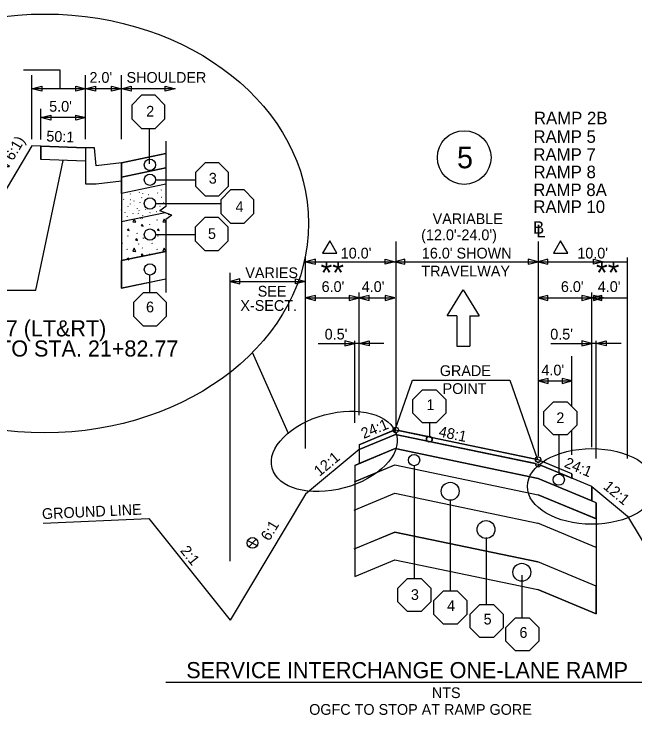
# Model space of a CAD drawing. Extents: x 4932 to 5887, y 4809 to 5473.
# Drawn here: x 5206.1 to 5275.5, y 5134.9 to 5213.3 of the extents above; entities that cross this region are included whole.
import ezdxf

# ---------------------------------------------------------------- set-up
doc = ezdxf.new("R2010")
doc.units = 0
for name, color, linetype in [('Level 2', 7, 'Continuous'), ('Level 20', 7, 'Continuous'), ('Level 25', 7, 'Continuous'), ('RD_QTY_Intermediate', 7, 'Continuous'), ('RD_QTY_Sub_Base', 7, 'Continuous'), ('RD_QTY_Surf_Course', 7, 'Continuous'), ('RD_SHT_Typical', 7, 'Continuous'), ('RD_TX_TypSect', 7, 'Continuous'), ('RD_XS_CurbBase', 7, 'Continuous'), ('RD_XS_CurbFront', 7, 'Continuous'), ('RD_XS_CurbTop', 7, 'Continuous'), ('RD_XS_ExGround', 7, 'Continuous'), ('typical_on', 7, 'Continuous')]:
    doc.layers.add(name, color=color, linetype=linetype)

msp = doc.modelspace()

# ---------------------------------------------------------------- linework, layer by layer
at = {"layer": 'Level 2'}
for p, q in [((5244.703, 5163.036), (5244.703, 5163.036)), ((5244.703, 5162.981), (5244.703, 5162.981))]:
    msp.add_line(p, q, dxfattribs=at)
at = {"layer": 'Level 20'}
for p, q in [((5254.517, 5179.537), (5256.339, 5182.451)), ((5256.339, 5182.451), (5258.123, 5179.527)), ((5255.609, 5179.536), (5254.517, 5179.537)), ((5255.609, 5179.536), (5255.609, 5176.136)), ((5257.066, 5179.527), (5258.123, 5179.527)), ((5257.066, 5179.527), (5257.066, 5176.127)), ((5255.609, 5176.136), (5257.066, 5176.127))]:
    msp.add_line(p, q, dxfattribs=at)
at = {"layer": 'Level 25'}
for p, q in [((5223.1, 5197.665), (5218.139, 5196.631)), ((5223.1, 5194.243), (5218.139, 5193.209)), ((5248.724, 5166.803), (5250.667, 5172.338)), ((5250.667, 5172.338), (5261.523, 5172.338)), ((5261.523, 5172.338), (5264.629, 5163.489))]:
    msp.add_line(p, q, dxfattribs=at)
msp.add_circle((5256.437, 5197.225), 3, dxfattribs=at)
at = {"layer": 'RD_QTY_Intermediate'}
for p, q in [((5218.139, 5195.036), (5223.1, 5196.058)), ((5223.1, 5196.058), (5223.1, 5194.243)), ((5223.1, 5196.058), (5223.1, 5196.058)), ((5218.139, 5193.769), (5218.139, 5195.036)), ((5218.139, 5193.209), (5218.139, 5194.871)), ((5218.139, 5194.871), (5218.139, 5193.769)), ((5223.1, 5194.243), (5218.139, 5193.209)), ((5223.1, 5194.243), (5223.1, 5194.243)), ((5264.696, 5161.376), (5248.724, 5164.704)), ((5244.203, 5161.011), (5248.696, 5162.883)), ((5244.203, 5162.82), (5244.203, 5161.011)), ((5248.696, 5162.883), (5264.694, 5159.55)), ((5270.694, 5158.858), (5264.696, 5161.376)), ((5264.694, 5159.55), (5271.193, 5156.842)), ((5271.193, 5158.65), (5270.694, 5158.86)), ((5271.193, 5156.842), (5271.193, 5158.65))]:
    msp.add_line(p, q, dxfattribs=at)
for points in [[(5248.724, 5164.704), (5244.703, 5163.029), (5244.203, 5162.82)], [(5270.694, 5158.86), (5270.694, 5158.858)]]:
    msp.add_lwpolyline(points, dxfattribs=at)
at = {"layer": 'RD_QTY_Sub_Base'}
for p, q in [((5218.154, 5185.715), (5223.1, 5186.732)), ((5223.1, 5186.732), (5223.1, 5183.64)), ((5223.1, 5186.732), (5223.1, 5186.732)), ((5218.161, 5182.616), (5218.154, 5185.715)), ((5223.1, 5183.64), (5218.161, 5182.616))]:
    msp.add_line(p, q, dxfattribs=at)
at = {"layer": 'RD_QTY_Surf_Course'}
for p, q in [((5218.139, 5196.631), (5223.1, 5197.665)), ((5223.1, 5197.665), (5223.1, 5196.069)), ((5223.1, 5197.665), (5223.1, 5197.665)), ((5223.1, 5197.665), (5223.1, 5197.665)), ((5218.139, 5195.036), (5218.139, 5196.631)), ((5223.1, 5196.069), (5218.139, 5195.036)), ((5248.76, 5166.292), (5244.703, 5164.602)), ((5264.402, 5163.033), (5248.76, 5166.292)), ((5244.703, 5163.029), (5248.724, 5164.704)), ((5244.703, 5164.602), (5244.703, 5163.029)), ((5248.724, 5164.704), (5264.696, 5161.376)), ((5264.696, 5161.376), (5270.694, 5158.86)), ((5270.694, 5158.86), (5270.694, 5160.473))]:
    msp.add_line(p, q, dxfattribs=at)
msp.add_lwpolyline([(5270.694, 5160.473), (5267.058, 5161.988), (5264.973, 5162.857)], dxfattribs=at)
msp.add_circle((5267, 5161.225), 0.63, dxfattribs=at)
msp.add_arc((5264.696, 5162.972), 0.3, 168.23191, 337.38014, dxfattribs=at)
at = {"layer": 'RD_SHT_Typical'}
for p, q in [((5208.143, 5198.515), (5203.033, 5189.997)), ((5214.139, 5198.298), (5208.143, 5198.515)), ((5209.139, 5198.479), (5209.139, 5196.988)), ((5209.139, 5196.988), (5209.139, 5198.479)), ((5209.139, 5198.479), (5214.139, 5198.298)), ((5209.139, 5198.479), (5214.139, 5198.298)), ((5214.139, 5198.298), (5209.139, 5198.479)), ((5223.1, 5199.043), (5223.1, 5191.766)), ((5214.139, 5198.298), (5214.139, 5196.807)), ((5214.139, 5196.807), (5209.139, 5196.988)), ((5214.139, 5196.807), (5209.139, 5196.988)), ((5218.139, 5196.631), (5218.139, 5182.6)), ((5218.139, 5195.036), (5223.1, 5196.058)), ((5218.139, 5193.209), (5218.139, 5190.958)), ((5223.1, 5190.29), (5223.1, 5182.128)), ((5246.645, 5165.937), (5248.724, 5166.803)), ((5248.501, 5166.71), (5246.645, 5165.937)), ((5252.387, 5166.04), (5249.083, 5166.728)), ((5244.703, 5164.602), (5248.76, 5166.292)), ((5244.703, 5164.602), (5248.76, 5166.292)), ((5244.703, 5165.128), (5246.645, 5165.937)), ((5246.645, 5165.937), (5244.703, 5165.128)), ((5248.76, 5166.292), (5252.266, 5165.561)), ((5244.703, 5165.128), (5244.703, 5163.029)), ((5244.703, 5165.128), (5244.703, 5164.602)), ((5252.72, 5165.467), (5264.402, 5163.033)), ((5244.703, 5164.602), (5238.706, 5159.604)), ((5244.203, 5162.82), (5248.724, 5164.704)), ((5268.472, 5161.888), (5264.629, 5163.489)), ((5268.472, 5161.888), (5264.966, 5163.349)), ((5244.176, 5160.999), (5248.696, 5162.883)), ((5244.203, 5162.82), (5244.203, 5150.416)), ((5264.402, 5163.033), (5264.696, 5162.972)), ((5270.694, 5160.473), (5264.696, 5162.972)), ((5264.696, 5162.972), (5264.973, 5162.857)), ((5268.472, 5161.888), (5268.472, 5161.4)), ((5268.472, 5161.4), (5268.472, 5161.888)), ((5271.193, 5158.65), (5264.672, 5161.367)), ((5270.694, 5160.473), (5270.694, 5158.858)), ((5270.694, 5160.473), (5274.692, 5157.141)), ((5238.706, 5159.604), (5230.27, 5145.544)), ((5244.153, 5157.823), (5248.674, 5159.707)), ((5271.216, 5156.833), (5264.694, 5159.55)), ((5271.193, 5158.65), (5271.193, 5146.229)), ((5274.692, 5157.141), (5282.696, 5143.801)), ((5221.185, 5156.901), (5230.27, 5145.544)), ((5271.193, 5153.657), (5264.672, 5156.374)), ((5244.16, 5153.492), (5248.68, 5155.376)), ((5244.203, 5150.416), (5248.674, 5152.279)), ((5271.193, 5149.327), (5264.654, 5152.052)), ((5271.193, 5146.229), (5264.654, 5148.953))]:
    msp.add_line(p, q, dxfattribs=at)
for points in [[(5223.036, 5191.049), (5218.139, 5190.029)], [(5223.1, 5186.732), (5218.139, 5185.699)], [(5223.1, 5183.634), (5218.139, 5182.6)], [(5248.724, 5166.803), (5263.699, 5163.683), (5264.629, 5163.489)], [(5248.76, 5166.292), (5264.696, 5162.972)], [(5264.401, 5163.537), (5263.699, 5163.683), (5252.8, 5165.954)], [(5248.724, 5164.704), (5264.696, 5161.376)], [(5248.696, 5162.883), (5264.694, 5159.55)], [(5264.973, 5162.857), (5267.058, 5161.988), (5268.472, 5161.399)], [(5268.472, 5161.399), (5268.472, 5161.4)], [(5248.674, 5159.707), (5264.672, 5156.374)], [(5248.674, 5155.377), (5264.672, 5152.044)], [(5248.674, 5152.279), (5264.672, 5148.946)]]:
    msp.add_lwpolyline(points, dxfattribs=at)
for centre, radius, start, end in [((5248.79, 5166.789), 0.3, 195.36042, 348.23191), ((5252.541, 5165.746), 0.332, 117.69811, 213.83802), ((5252.541, 5165.746), 0.332, 302.6258, 38.76571), ((5264.694, 5163.476), 0.3, 168.23191, 334.96624)]:
    msp.add_arc(centre, radius, start, end, dxfattribs=at)
at = {"layer": 'RD_TX_TypSect'}
for p, q in [((5207.207, 5207.028), (5211.242, 5207.028)), ((5208.143, 5199.278), (5208.143, 5206.443)), ((5211.242, 5207.028), (5211.242, 5204.919)), ((5214.141, 5199.278), (5214.141, 5206.443)), ((5218.139, 5199.278), (5218.139, 5206.443)), ((5214.141, 5204.911), (5208.143, 5204.911)), ((5218.139, 5204.911), (5214.141, 5204.911)), ((5224.137, 5204.911), (5218.139, 5204.911)), ((5209.139, 5199.242), (5209.139, 5202.669)), ((5214.141, 5201.681), (5209.139, 5201.681)), ((5221.261, 5196.531), (5221.261, 5200.482)), ((5208.575, 5182.385), (5211.639, 5196.897)), ((5221.948, 5194.738), (5226.359, 5194.738)), ((5219.139, 5193.139), (5219.128, 5193.172)), ((5220.141, 5193.329), (5220.13, 5193.363)), ((5220.529, 5193.185), (5220.518, 5193.218)), ((5221.116, 5193.105), (5221.15, 5193.098)), ((5222.189, 5193.232), (5222.178, 5193.265)), ((5222.623, 5193.587), (5222.612, 5193.621)), ((5218.394, 5192.52), (5218.383, 5192.553)), ((5219.12, 5192.548), (5219.155, 5192.541)), ((5219.528, 5192.367), (5219.545, 5192.384)), ((5220.234, 5192.184), (5220.223, 5192.218)), ((5220.396, 5192.73), (5220.412, 5192.746)), ((5222.573, 5192.796), (5222.608, 5192.788)), ((5218.211, 5191.785), (5218.228, 5191.802)), ((5218.878, 5191.719), (5218.895, 5191.735)), ((5219.145, 5192.018), (5219.161, 5192.035)), ((5219.628, 5191.852), (5219.645, 5191.868)), ((5219.895, 5191.545), (5219.888, 5191.537)), ((5219.908, 5191.552), (5219.895, 5191.545)), ((5220.854, 5191.417), (5220.843, 5191.45)), ((5221.948, 5192.084), (5229.236, 5192.084)), ((5223.1, 5191.766), (5222.416, 5191.28)), ((5222.445, 5191.785), (5222.462, 5191.802)), ((5222.845, 5192.168), (5222.862, 5192.184)), ((5218.146, 5191.355), (5218.135, 5191.388)), ((5218.555, 5191.096), (5218.572, 5191.113)), ((5218.813, 5190.638), (5218.802, 5190.671)), ((5219.076, 5191.324), (5219.065, 5191.357)), ((5219.465, 5190.979), (5219.453, 5191.012)), ((5220.048, 5190.984), (5220.037, 5191.017)), ((5220.11, 5191.262), (5220.099, 5191.296)), ((5220.545, 5190.716), (5220.534, 5190.749)), ((5221.326, 5191.049), (5221.343, 5191.066)), ((5222.015, 5191.193), (5222.049, 5191.186)), ((5223.777, 5190.772), (5222.416, 5191.28)), ((5223.777, 5190.772), (5223.1, 5190.29)), ((5223.411, 5190.849), (5223.383, 5190.807)), ((5223.439, 5190.865), (5223.411, 5190.823)), ((5218.208, 5189.988), (5218.197, 5190.022)), ((5218.679, 5190.152), (5218.696, 5190.169)), ((5219.284, 5190.245), (5219.301, 5190.261)), ((5219.754, 5189.997), (5219.611, 5190.266)), ((5220.278, 5190.45), (5220.312, 5190.443)), ((5220.502, 5190.346), (5220.474, 5190.409)), ((5222.159, 5190.185), (5222.131, 5190.248)), ((5221.285, 5189.738), (5221.257, 5189.696)), ((5218.88, 5188.409), (5218.852, 5188.472)), ((5219.943, 5188.696), (5219.915, 5188.759)), ((5221.948, 5188.608), (5226.359, 5188.608)), ((5222.229, 5188.409), (5222.201, 5188.472)), ((5218.244, 5187.598), (5218.216, 5187.661)), ((5220.062, 5187.582), (5220.034, 5187.54)), ((5220.09, 5187.598), (5220.062, 5187.556)), ((5220.567, 5188.234), (5220.56, 5188.171)), ((5221.593, 5187.598), (5221.565, 5187.661)), ((5248.79, 5187.854), (5248.79, 5167.151)), ((5264.694, 5187.854), (5264.694, 5163.838)), ((5218.81, 5186.919), (5218.782, 5186.982)), ((5220.502, 5187.08), (5220.474, 5187.143)), ((5222.159, 5186.919), (5222.131, 5186.982)), ((5221.285, 5186.472), (5221.257, 5186.43)), ((5238.706, 5164.692), (5238.706, 5186.061)), ((5274.692, 5163.609), (5274.692, 5186.061)), ((5238.706, 5185.575), (5248.702, 5185.575)), ((5248.702, 5185.575), (5264.696, 5185.575)), ((5264.696, 5185.575), (5274.692, 5185.575)), ((5221.312, 5182.098), (5221.312, 5184.098)), ((5230.27, 5152.11), (5230.27, 5184.348)), ((5230.27, 5183.384), (5238.706, 5183.384)), ((5204.54, 5182.385), (5208.575, 5182.385)), ((5244.703, 5168.43), (5244.703, 5182.156)), ((5270.694, 5164.873), (5270.694, 5182.156)), ((5238.706, 5181.538), (5244.703, 5181.538)), ((5244.703, 5181.538), (5248.702, 5181.538)), ((5264.696, 5181.538), (5270.694, 5181.538)), ((5270.694, 5181.538), (5274.692, 5181.538)), ((5244.203, 5167.573), (5244.203, 5176.735)), ((5271.193, 5163.609), (5271.193, 5176.735)), ((5240.125, 5176.46), (5244.203, 5176.46)), ((5247.468, 5176.46), (5244.203, 5176.46)), ((5266.106, 5176.46), (5270.694, 5176.46)), ((5273.959, 5176.46), (5270.694, 5176.46)), ((5236.773, 5166.446), (5232.791, 5175.443)), ((5268.473, 5169.393), (5268.473, 5175.015)), ((5264.726, 5172.26), (5268.473, 5172.26)), ((5252.542, 5167.562), (5252.542, 5166.078)), ((5268.473, 5164.002), (5268.473, 5166.76)), ((5267.058, 5161.848), (5267.058, 5166.23)), ((5250.879, 5150.173), (5250.879, 5162.816)), ((5254.895, 5148.789), (5254.895, 5158.998)), ((5248.674, 5155.377), (5244.203, 5153.51)), ((5258.944, 5147.277), (5258.944, 5154.75)), ((5232.24, 5154.427), (5233.312, 5153.88)), ((5232.363, 5153.734), (5233.189, 5154.578)), ((5244.203, 5153.51), (5244.203, 5150.416)), ((5244.203, 5150.416), (5248.674, 5152.279)), ((5248.674, 5152.279), (5264.654, 5148.95)), ((5271.193, 5149.327), (5264.672, 5152.044)), ((5262.92, 5145.784), (5262.92, 5150.55)), ((5271.193, 5146.229), (5271.193, 5149.327)), ((5223.094, 5138.601), (5281.463, 5138.601))]:
    msp.add_line(p, q, dxfattribs=at)
for points in [[(5209.246, 5205.186), (5209.246, 5204.636), (5208.143, 5204.911)], [(5213.038, 5204.636), (5213.038, 5205.186), (5214.141, 5204.911)], [(5215.243, 5205.186), (5215.243, 5204.636), (5214.141, 5204.911)], [(5217.037, 5204.636), (5217.037, 5205.186), (5218.139, 5204.911)], [(5219.242, 5205.186), (5219.242, 5204.636), (5218.139, 5204.911)], [(5223.034, 5204.636), (5223.034, 5205.186), (5224.137, 5204.911)], [(5210.241, 5201.956), (5210.241, 5201.406), (5209.139, 5201.681)], [(5213.038, 5201.406), (5213.038, 5201.956), (5214.141, 5201.681)], [(5241.422, 5187.91), (5240.623, 5186.525), (5242.221, 5186.525)], [(5267.214, 5187.91), (5266.415, 5186.525), (5268.013, 5186.525)], [(5239.808, 5185.3), (5239.808, 5185.85), (5238.706, 5185.575)], [(5247.599, 5185.3), (5247.599, 5185.85), (5248.702, 5185.575)], [(5249.804, 5185.3), (5249.804, 5185.85), (5248.702, 5185.575)], [(5263.593, 5185.85), (5263.593, 5185.3), (5264.696, 5185.575)], [(5265.799, 5185.3), (5265.799, 5185.85), (5264.696, 5185.575)], [(5270.882, 5185.3), (5270.882, 5185.85), (5271.984, 5185.575)], [(5231.373, 5183.11), (5231.373, 5183.659), (5230.27, 5183.384)], [(5237.603, 5183.11), (5237.603, 5183.659), (5238.706, 5183.384)], [(5239.808, 5181.263), (5239.808, 5181.813), (5238.706, 5181.538)], [(5243.601, 5181.813), (5243.601, 5181.263), (5244.703, 5181.538)], [(5245.806, 5181.263), (5245.806, 5181.813), (5244.703, 5181.538)], [(5247.599, 5181.813), (5247.599, 5181.263), (5248.702, 5181.538)], [(5265.799, 5181.263), (5265.799, 5181.813), (5264.696, 5181.538)], [(5269.591, 5181.813), (5269.591, 5181.263), (5270.694, 5181.538)], [(5271.796, 5181.263), (5271.796, 5181.813), (5270.694, 5181.538)], [(5270.882, 5181.813), (5270.882, 5181.263), (5271.984, 5181.538)], [(5243.101, 5176.735), (5243.101, 5176.186), (5244.203, 5176.46)], [(5245.806, 5176.735), (5245.806, 5176.186), (5244.703, 5176.46)], [(5269.591, 5176.735), (5269.591, 5176.186), (5270.694, 5176.46)], [(5272.296, 5176.735), (5272.296, 5176.186), (5271.193, 5176.46)], [(5265.828, 5171.985), (5265.828, 5172.535), (5264.726, 5172.26)], [(5267.37, 5172.535), (5267.37, 5171.985), (5268.473, 5172.26)]]:
    msp.add_lwpolyline(points, close=True, dxfattribs=at)
for points in [[(5219.518, 5190.246), (5219.418, 5190.025), (5219.747, 5189.997)], [(5223.1, 5190.004), (5222.915, 5190.353), (5222.768, 5190.025), (5223.096, 5189.997)], [(5219.018, 5189.056), (5218.935, 5189.231), (5218.795, 5189.126), (5219.018, 5189.056)], [(5220.551, 5189.556), (5220.467, 5189.731), (5220.327, 5189.626), (5220.551, 5189.556)], [(5222.368, 5189.056), (5222.284, 5189.231), (5222.144, 5189.126), (5222.368, 5189.056)], [(5219.929, 5187.962), (5219.845, 5188.137), (5219.705, 5188.032), (5219.929, 5187.962)], [(5223.1, 5188.066), (5223.054, 5188.032), (5223.1, 5188.018)], [(5219.754, 5186.73), (5219.565, 5187.087), (5219.418, 5186.758), (5219.747, 5186.73)], [(5223.1, 5186.738), (5222.915, 5187.087), (5222.768, 5186.758), (5223.096, 5186.73)], [(5219.009, 5185.811), (5218.935, 5185.965), (5218.795, 5185.86), (5218.975, 5185.804)], [(5220.551, 5186.29), (5220.467, 5186.465), (5220.327, 5186.36), (5220.551, 5186.29)], [(5264.672, 5152.044), (5264.654, 5152.048), (5248.674, 5155.377)], [(5264.654, 5148.95), (5264.654, 5148.953)], [(5264.654, 5148.953), (5264.672, 5148.946), (5271.193, 5146.229)]]:
    msp.add_lwpolyline(points, dxfattribs=at)
for centre, radius in [((5221.319, 5196.408), 0.63), ((5221.319, 5194.738), 0.63), ((5221.319, 5192.084), 0.63), ((5221.319, 5188.608), 0.63), ((5221.319, 5184.727), 0.63), ((5248.79, 5166.789), 0.3), ((5252.541, 5165.746), 0.332), ((5250.842, 5163.421), 0.63), ((5264.694, 5163.476), 0.3), ((5267, 5161.225), 0.63), ((5254.876, 5159.932), 1), ((5258.874, 5155.658), 1), ((5232.781, 5154.159), 0.6), ((5262.877, 5150.879), 1), ((5262.877, 5150.879), 1)]:
    msp.add_circle(centre, radius, dxfattribs=at)
for centre, major_axis, ratio in [((5209.58, 5189.865), (-29.478, 0), 0.793631), ((5241.924, 5164.384), (-6.951, -1.869), 0.587586), ((5270.694, 5160.473), (-7.198, 0), 0.587586)]:
    msp.add_ellipse(centre, major_axis=major_axis, ratio=ratio, dxfattribs=at)
at = {"layer": 'RD_XS_CurbBase'}
for p, q in [((5214.139, 5198.298), (5214.139, 5194.298)), ((5215.306, 5194.298), (5218.139, 5194.631)), ((5214.139, 5194.298), (5215.306, 5194.298))]:
    msp.add_line(p, q, dxfattribs=at)
at = {"layer": 'RD_XS_CurbFront'}
msp.add_line((5218.139, 5196.631), (5218.139, 5195.135), dxfattribs=at)
at = {"layer": 'RD_XS_CurbTop'}
for p, q in [((5215.139, 5198.298), (5214.139, 5198.298)), ((5215.306, 5196.298), (5215.139, 5198.298)), ((5218.139, 5196.631), (5215.306, 5196.298))]:
    msp.add_line(p, q, dxfattribs=at)
at = {"layer": 'RD_XS_ExGround'}
msp.add_line((5209.392, 5156.364), (5221.185, 5156.901), dxfattribs=at)
at = {"layer": 'typical_on'}
for points in [[(5219.295, 5203.093), (5219.295, 5201.563), (5220.376, 5200.482), (5221.906, 5200.482), (5222.987, 5201.563), (5222.987, 5203.093), (5221.906, 5204.175), (5220.376, 5204.175)], [(5226.41, 5195.546), (5226.41, 5194.017), (5227.492, 5192.935), (5229.021, 5192.935), (5230.103, 5194.017), (5230.103, 5195.546), (5229.021, 5196.628), (5227.492, 5196.628)], [(5229.236, 5192.515), (5229.236, 5190.986), (5230.317, 5189.904), (5231.847, 5189.904), (5232.928, 5190.986), (5232.928, 5192.515), (5231.847, 5193.597), (5230.317, 5193.597)], [(5226.382, 5189.451), (5226.382, 5187.921), (5227.463, 5186.84), (5228.993, 5186.84), (5230.075, 5187.921), (5230.075, 5189.451), (5228.993, 5190.533), (5227.463, 5190.533)], [(5219.479, 5181.016), (5219.479, 5179.486), (5220.561, 5178.405), (5222.09, 5178.405), (5223.172, 5179.486), (5223.172, 5181.016), (5222.091, 5182.098), (5220.561, 5182.098)], [(5254.388, 5170.173), (5254.388, 5168.643), (5253.307, 5167.562), (5251.777, 5167.562), (5250.696, 5168.643), (5250.696, 5170.173), (5251.777, 5171.255), (5253.307, 5171.255)], [(5269.024, 5168.841), (5269.024, 5167.312), (5267.943, 5166.23), (5266.413, 5166.23), (5265.332, 5167.312), (5265.332, 5168.841), (5266.413, 5169.923), (5267.943, 5169.923)], [(5252.725, 5149.092), (5252.725, 5147.562), (5251.644, 5146.481), (5250.114, 5146.48), (5249.032, 5147.562), (5249.032, 5149.092), (5250.114, 5150.173), (5251.644, 5150.173)], [(5256.741, 5147.708), (5256.741, 5146.178), (5255.66, 5145.096), (5254.13, 5145.096), (5253.048, 5146.178), (5253.048, 5147.708), (5254.13, 5148.789), (5255.66, 5148.789)], [(5260.79, 5146.195), (5260.79, 5144.666), (5259.709, 5143.584), (5258.179, 5143.584), (5257.098, 5144.666), (5257.098, 5146.195), (5258.179, 5147.277), (5259.709, 5147.277)], [(5264.766, 5144.703), (5264.767, 5143.173), (5263.685, 5142.092), (5262.155, 5142.091), (5261.074, 5143.173), (5261.074, 5144.703), (5262.155, 5145.784), (5263.685, 5145.784)]]:
    msp.add_lwpolyline(points, close=True, dxfattribs=at)

# ---------------------------------------------------------------- texts
at = {"layer": 'Level 25'}
msp.add_text('50:1', height=1.2, rotation=357.93101, dxfattribs=at).set_placement((5209.733, 5199.023))
msp.add_text('5', height=2.4, dxfattribs=at).set_placement((5255.633, 5196.025))
at = {"layer": 'RD_TX_TypSect'}
for s, height, p in [("2.0'", 1.2, (5214.568, 5205.573)), ('SHOULDER', 1.2, (5218.709, 5205.573)), ("5.0'", 1.2, (5210.068, 5202.343)), ('2', 1.2, (5220.906, 5201.796)), ('RAMP 2B', 1.4, (5264.229, 5200.94)), ('RAMP 5', 1.4, (5264.177, 5198.862)), ('RAMP 7', 1.4, (5264.166, 5196.858)), ('RAMP 8', 1.4, (5264.177, 5194.916)), ('3', 1.2, (5227.903, 5194.312)), ('RAMP 8A', 1.4, (5264.154, 5192.92)), ('4', 1.2, (5230.887, 5191.133)), ('RAMP 10', 1.4, (5264.167, 5191.031)), ('B', 1.4, (5264.122, 5188.7)), ('5', 1.2, (5227.806, 5188.118)), ('L', 1.4, (5264.494, 5188.313)), ("10.0'", 1.2, (5242.642, 5185.939)), ("16.0' SHOWN", 1.2, (5251.706, 5185.939)), ("10.0'", 1.2, (5269.072, 5185.939)), ('**', 2.5, (5240.394, 5183.112)), ('**', 2.5, (5271.168, 5183.112)), ('VARIES', 1.2, (5231.984, 5183.748)), ('TRAVELWAY', 1.2, (5251.656, 5183.939)), ('SEE', 1.2, (5233.365, 5181.686)), ("6.0'", 1.2, (5240.505, 5182.199)), ("4.0'", 1.2, (5244.987, 5182.199)), ("6.0'", 1.2, (5267.241, 5182.199)), ("4.0'", 1.2, (5271.363, 5182.199)), ('X-SECT.', 1.2, (5231.429, 5180.089)), ('6', 1.2, (5220.888, 5179.923)), ('RAMP 7 (LT&RT)', 1.8, (5197.591, 5177.239)), ("0.5'", 1.2, (5240.848, 5176.887)), ("0.5'", 1.2, (5266.052, 5176.887)), ('STA. 21+16.64 TO STA. 21+82.77', 1.8, (5187.57, 5174.986)), ('GRADE', 1.2, (5253.712, 5172.806)), ("4.0'", 1.2, (5265.067, 5172.875)), ('POINT', 1.2, (5254.024, 5170.806)), ('1', 1.2, (5252.224, 5168.999)), ('2', 1.2, (5266.733, 5167.545)), ('3', 1.2, (5250.483, 5147.785)), ('4', 1.2, (5254.529, 5146.558)), ('5', 1.2, (5258.606, 5145.046)), ('6', 1.2, (5262.61, 5143.553)), ('SERVICE INTERCHANGE ONE-LANE RAMP', 1.8, (5225.387, 5139.047)), ('NTS', 1.2, (5252.821, 5136.823)), ('OGFC TO STOP AT RAMP GORE', 1.2, (5239.115, 5134.951))]:
    msp.add_text(s, height=height, dxfattribs=at).set_placement(p)
for s, rotation, p in [('(SHOWN 6:1)', 59.03624, (5202.338, 5190.673)), ('VARIABLE', 0.00163, (5252.907, 5189.784)), ("(12.0'-24.0')", 0.00163, (5251.629, 5187.984)), ('24:1', 22.61905, (5245.213, 5165.771)), ('48:1', 348.23171, (5253.514, 5166.062)), ('12:1', 39.80557, (5240.268, 5161.531)), ('24:1', 337.38014, (5267.53, 5162.675)), ('12:1', 320.19386, (5271.89, 5160.304)), ('GROUND LINE', 2.60954, (5209.287, 5156.815)), ('6:1', 59.03624, (5234.658, 5154.292)), ('2:1', 308.65981, (5224.65, 5153.275))]:
    msp.add_text(s, height=1.2, rotation=rotation, dxfattribs=at).set_placement(p)

doc.saveas('drawing.dxf')
